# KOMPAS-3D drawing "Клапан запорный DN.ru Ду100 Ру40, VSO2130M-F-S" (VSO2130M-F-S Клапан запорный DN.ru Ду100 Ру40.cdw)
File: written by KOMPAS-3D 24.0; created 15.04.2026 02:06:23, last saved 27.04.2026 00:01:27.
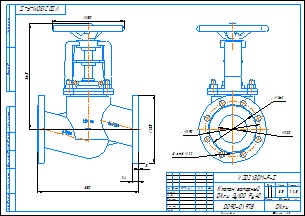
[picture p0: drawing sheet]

Document properties: Автор: DN.ru; Форматы листов документа: A3; Полное имя файла: VSO2130M-F-S Клапан запорный DN.ru Ду100 Ру40.m3d; Масса: 35; Наименование: Клапан запорный DN.ru Ду100 Ру40; Количество листов документа: 1; Примечание: D090-01978

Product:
- Part/product: Клапан запорный DN.ru Ду100 Ру40  | designation VSO2130M-F-S
    Масса: 35
    Раздел спецификации: Прочие изделия
    Примечание: D090-01978

Views: Вид 1, Вид:1, Проекционный вид 2
Referenced files in C:\Работа\VSO2130M-F-S Клапан запорный DN.ru\DN20\: VSO2130M-F-S DN20 PN40  Клапан запорный сильфонный DN.ru.m3d
Referenced files in C:\Работа\VSO2130M-F-S Клапан запорный DN.ru\DN100\: VSO2130M-F-S Клапан запорный DN.ru Ду100 Ру40.m3d
Referenced files in C:\Program Files\ASCON\KOMPAS-3D v24\Templates\: Чертеж_DN.ru.cdt
Referenced files in C:\Работа\ГОТОВЫЕ ИСХОДНИКИ\VSO2130M-F-S Клапан запорный сильфонный DN.ru Ду15-100 Ру40\DN100\: VSO2130M-F-S Клапан запорный DN.ru Ду100 Ру40.m3d
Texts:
  VSO2130M-F-S
  Чертеж_DN.ru.cdt
  Клапан запорный
  DN.ru Ду100 Ру40
  Клапан запорный DN.ru Ду100 Ру40
  VSO2130M-F-S  Клапан запорный DN.ru Ду100 Ру40
Dimensions and other numbers on the sheet: 0; 3; 2; 4; 235; 24; 350; 365; 250; 1; 5; 100; 162; 190; 8 отв.; 22; 1:2,5; 35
